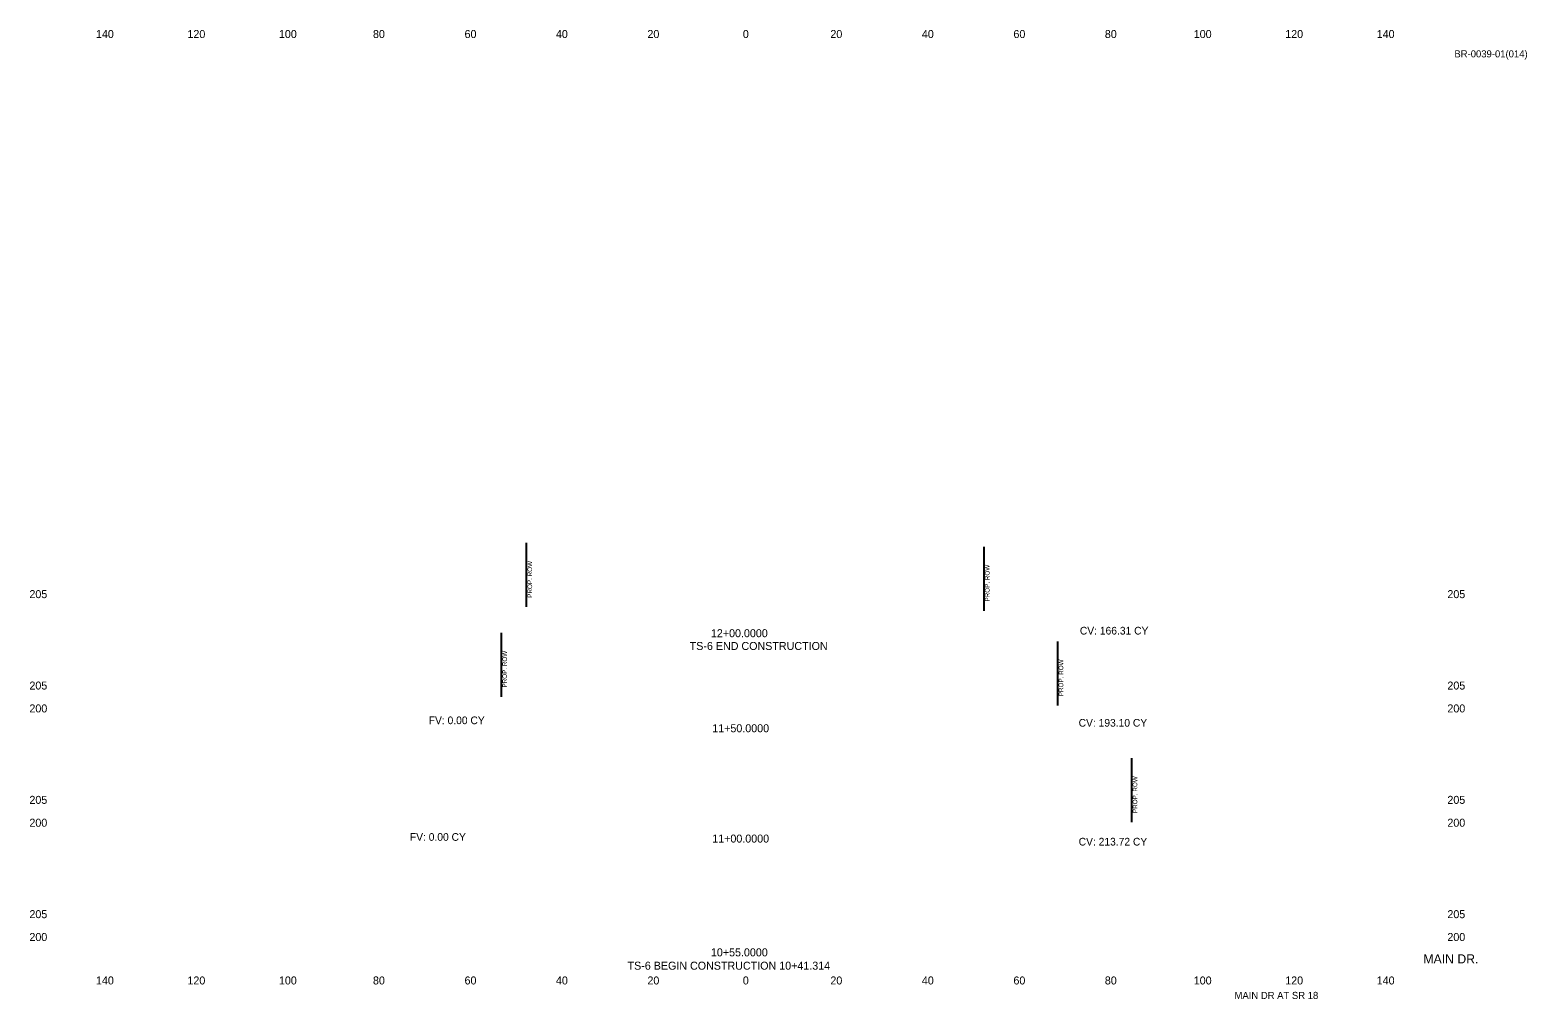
# Model space of a CAD drawing. Extents: x 21486 to 21814, y 6472 to 6684.
import ezdxf

# ---------------------------------------------------------------- set-up
doc = ezdxf.new("R2010")
doc.units = 0
for name, color, linetype in [('SHEET_BORDER_TX', 7, 'Continuous'), ('SHEET_PROJ_NUMBER', 7, 'Continuous'), ('XS_P_ROW', 7, 'Continuous'), ('XS_SHEET_EW_TX_VOLUME', 7, 'Continuous'), ('XS_SHEET_LABELS_ELEVATION', 7, 'Continuous'), ('XS_SHEET_LABELS_OFFSET', 7, 'Continuous'), ('XS_SHEET_LABELS_STATION', 7, 'Continuous')]:
    doc.layers.add(name, color=color, linetype=linetype)

msp = doc.modelspace()

# ---------------------------------------------------------------- linework, layer by layer
at = {"layer": 'XS_P_ROW'}
for p, q in [((21594.84, 6557.91), (21594.84, 6571.91)), ((21694.84, 6557.09), (21694.84, 6571.09)), ((21589.34, 6538.27), (21589.34, 6552.27)), ((21710.96, 6536.38), (21710.96, 6550.38)), ((21727.14, 6510.83), (21727.14, 6524.83))]:
    msp.add_line(p, q, dxfattribs=at)

# ---------------------------------------------------------------- texts
at = {"layer": 'SHEET_BORDER_TX'}
for s, height, p in [('MAIN DR.', 2, (21790.89, 6479.93)), ('MAIN DR AT SR 18', 1.55, (21749.6, 6472.17))]:
    msp.add_text(s, height=height, dxfattribs=at).set_placement(p)
at = {"layer": 'SHEET_PROJ_NUMBER'}
msp.add_text('BR-0039-01(014)', height=1.55, dxfattribs=at).set_placement((21797.67, 6678.1))
at = {"layer": 'XS_P_ROW'}
for p in [(21596.04, 6559.91), (21696.04, 6559.09), (21590.54, 6540.27), (21712.16, 6538.38), (21728.34, 6512.83)]:
    msp.add_text('PROP. ROW', height=1, rotation=90, dxfattribs=at).set_placement(p)
at = {"layer": 'XS_SHEET_EW_TX_VOLUME'}
for s, p in [('CV: 166.31 CY', (21715.79, 6551.88)), ('FV: 0.00 CY', (21573.44, 6532.27)), ('CV: 193.10 CY', (21715.52, 6531.73)), ('FV: 0.00 CY', (21569.32, 6506.76)), ('CV: 213.72 CY', (21715.53, 6505.73))]:
    msp.add_text(s, height=1.68, dxfattribs=at).set_placement(p)
at = {"layer": 'XS_SHEET_LABELS_ELEVATION'}
for s, p in [('  205  ', (21484.84, 6559.84)), ('  205  ', (21794.84, 6559.84)), ('  205  ', (21484.84, 6539.84)), ('  205  ', (21794.84, 6539.84)), ('  200  ', (21484.84, 6534.84)), ('  200  ', (21794.84, 6534.84)), ('  205  ', (21484.84, 6514.84)), ('  205  ', (21794.84, 6514.84)), ('  200  ', (21484.84, 6509.84)), ('  200  ', (21794.84, 6509.84)), ('  205  ', (21484.84, 6489.84)), ('  205  ', (21794.84, 6489.84)), ('  200  ', (21484.84, 6484.84)), ('  200  ', (21794.84, 6484.84))]:
    msp.add_text(s, height=1.75, dxfattribs=at).set_placement(p)
at = {"layer": 'XS_SHEET_LABELS_OFFSET'}
for s, p in [('  140  ', (21499.39, 6682.34)), ('  120  ', (21519.39, 6682.34)), ('  100  ', (21539.39, 6682.34)), ('  80  ', (21559.95, 6682.34)), ('  60  ', (21579.97, 6682.34)), ('  40  ', (21599.95, 6682.34)), ('  20  ', (21619.95, 6682.34)), ('  0  ', (21640.81, 6682.34)), ('  0  ', (21640.81, 6682.34)), ('  20  ', (21659.95, 6682.34)), ('  40  ', (21679.95, 6682.34)), ('  60  ', (21699.97, 6682.34)), ('  80  ', (21719.95, 6682.34)), ('  100  ', (21739.39, 6682.34)), ('  120  ', (21759.39, 6682.34)), ('  140  ', (21779.39, 6682.34)), ('  140  ', (21499.39, 6475.34)), ('  120  ', (21519.39, 6475.34)), ('  100  ', (21539.39, 6475.34)), ('  80  ', (21559.95, 6475.34)), ('  60  ', (21579.97, 6475.34)), ('  40  ', (21599.95, 6475.34)), ('  20  ', (21619.95, 6475.34)), ('  0  ', (21640.81, 6475.34)), ('  0  ', (21640.81, 6475.34)), ('  20  ', (21659.95, 6475.34)), ('  40  ', (21679.95, 6475.34)), ('  60  ', (21699.97, 6475.34)), ('  80  ', (21719.95, 6475.34)), ('  100  ', (21739.39, 6475.34)), ('  120  ', (21759.39, 6475.34)), ('  140  ', (21779.39, 6475.34))]:
    msp.add_text(s, height=1.75, dxfattribs=at).set_placement(p)
at = {"layer": 'XS_SHEET_LABELS_STATION'}
for s, p in [('  12+00.0000  ', (21633.83, 6551.29)), ('TS-6 END CONSTRUCTION', (21630.49, 6548.5)), ('  11+50.0000  ', (21634.12, 6530.5)), ('  11+00.0000  ', (21634.12, 6506.37)), ('  10+55.0000  ', (21633.83, 6481.49)), (' TS-6 BEGIN CONSTRUCTION 10+41.314', (21616.26, 6478.57))]:
    msp.add_text(s, height=1.75, dxfattribs=at).set_placement(p)

doc.saveas('drawing.dxf')
